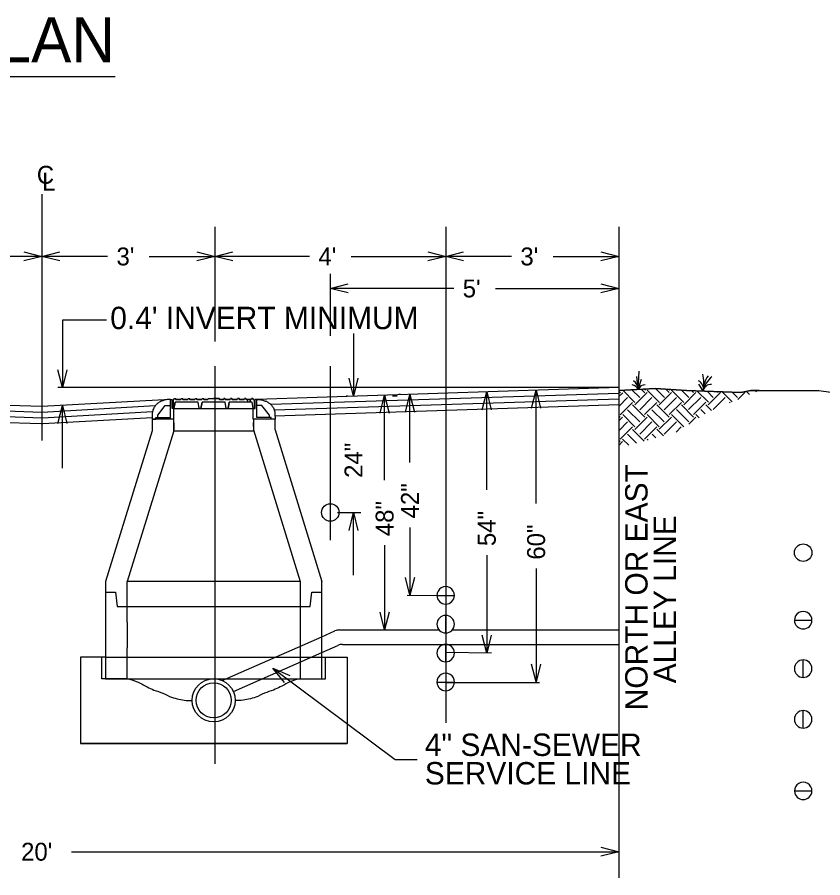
# Model space of a CAD drawing. Extents: x 524397 to 525117, y 3701341 to 3701821.
# Drawn here: x 524531 to 524603, y 3701447.4 to 3701524.2 of the extents above; entities that cross this region are included whole.
import ezdxf

# ---------------------------------------------------------------- set-up
doc = ezdxf.new("R2010")
doc.units = 0
doc.layers.add('Level 1', color=7, linetype='Continuous')
doc.layers.add('Level 11', color=7, linetype='Continuous')

msp = doc.modelspace()

# ---------------------------------------------------------------- linework, layer by layer
at = {"layer": 'Level 1'}
for p, q in [((524526.598, 3701518.966), (524539.734, 3701518.966)), ((524533.168, 3701508.449), (524533.168, 3701486.42)), ((524548.636, 3701505.51), (524548.636, 3701495.288)), ((524569.261, 3701505.51), (524569.261, 3701461.218)), ((524584.73, 3701505.51), (524584.73, 3701447.362)), ((524558.949, 3701501.319), (524558.949, 3701495.77)), ((524548.636, 3701493.058), (524548.636, 3701457.545)), ((524558.949, 3701493.058), (524558.949, 3701477.535)), ((524586.467, 3701490.993), (524586.344, 3701492.151)), ((524586.467, 3701490.993), (524586.554, 3701492.625)), ((524586.467, 3701490.993), (524586.765, 3701491.923)), ((524533.168, 3701489.455), (524486.759, 3701491.156)), ((524533.151, 3701488.939), (524487.926, 3701490.601)), ((524584.73, 3701491.156), (524534.586, 3701491.156)), ((524584.73, 3701491.156), (524552.385, 3701490.108)), ((524584.73, 3701490.64), (524553.646, 3701489.633)), ((524587.984, 3701491.074), (524584.73, 3701490.9)), ((524584.73, 3701490.9), (524587.984, 3701491.074)), ((524584.73, 3701490.9), (524584.73, 3701485.763)), ((524584.73, 3701490.847), (524584.875, 3701490.702)), ((524584.73, 3701490.354), (524585.078, 3701490.702)), ((524585.08, 3701490.919), (524586.172, 3701489.827)), ((524585.911, 3701490.963), (524586.609, 3701490.265)), ((524586.164, 3701489.616), (524587.258, 3701490.71)), ((524586.741, 3701491.008), (524587.047, 3701490.702)), ((524587.047, 3701490.921), (524587.156, 3701491.03)), ((524587.274, 3701490.929), (524588.368, 3701489.835)), ((524590.772, 3701490.9), (524587.984, 3701491.074)), ((524587.984, 3701491.074), (524590.772, 3701490.9)), ((524588.005, 3701491.073), (524588.805, 3701490.273)), ((524588.352, 3701489.616), (524589.446, 3701490.71)), ((524588.938, 3701491.015), (524589.243, 3701490.71)), ((524589.227, 3701490.928), (524589.291, 3701490.993)), ((524589.446, 3701490.928), (524590.539, 3701489.835)), ((524590.321, 3701490.929), (524590.977, 3701490.272)), ((524590.532, 3701489.624), (524591.626, 3701490.717)), ((524595.652, 3701490.727), (524590.772, 3701490.9)), ((524590.772, 3701490.9), (524595.652, 3701490.727)), ((524591.24, 3701490.884), (524591.414, 3701490.71)), ((524591.711, 3701490.867), (524592.735, 3701489.843)), ((524592.618, 3701490.835), (524593.173, 3701490.28)), ((524592.719, 3701489.624), (524593.813, 3701490.717)), ((524593.526, 3701490.802), (524593.61, 3701490.718)), ((524593.962, 3701490.787), (524594.863, 3701489.886)), ((524594.87, 3701490.754), (524595.345, 3701490.28)), ((524595.363, 3701490.095), (524595.993, 3701490.725)), ((524596.523, 3701490.9), (524595.652, 3701490.727)), ((524595.652, 3701490.727), (524596.523, 3701490.9)), ((524595.753, 3701490.747), (524595.782, 3701490.717)), ((524596.131, 3701490.822), (524596.417, 3701490.536)), ((524597.29, 3701490.9), (524596.523, 3701490.9)), ((524596.523, 3701490.9), (524598.439, 3701490.9)), ((524596.928, 3701490.9), (524597.034, 3701490.794)), ((524598.439, 3701490.9), (524599.485, 3701490.9)), ((524599.485, 3701490.9), (524602.622, 3701490.9)), ((524602.622, 3701490.9), (524606.455, 3701490.379)), ((524533.134, 3701488.423), (524487.994, 3701490.083)), ((524544.655, 3701490.108), (524533.168, 3701489.455)), ((524544.655, 3701490.108), (524544.655, 3701490.108)), ((524544.655, 3701490.108), (524544.817, 3701490.108)), ((524544.655, 3701489.545), (524544.655, 3701490.108)), ((524544.816, 3701489.303), (524544.817, 3701490.108)), ((524544.896, 3701490.108), (524544.896, 3701489.303)), ((524544.978, 3701490.108), (524544.896, 3701490.108)), ((524544.977, 3701489.303), (524545.076, 3701489.867)), ((524544.978, 3701490.108), (524545.008, 3701490.188)), ((524545.008, 3701490.188), (524545.128, 3701490.188)), ((524547.132, 3701489.867), (524545.076, 3701489.867)), ((524545.158, 3701490.108), (524545.128, 3701490.188)), ((524545.604, 3701490.108), (524545.158, 3701490.108)), ((524545.604, 3701490.108), (524545.634, 3701490.188)), ((524545.634, 3701490.188), (524545.749, 3701490.188)), ((524545.778, 3701490.108), (524545.749, 3701490.188)), ((524546.216, 3701490.108), (524545.778, 3701490.108)), ((524546.216, 3701490.108), (524546.245, 3701490.188)), ((524546.245, 3701490.188), (524546.376, 3701490.188)), ((524546.406, 3701490.108), (524546.376, 3701490.188)), ((524546.849, 3701490.108), (524546.406, 3701490.108)), ((524546.849, 3701490.108), (524546.879, 3701490.188)), ((524546.879, 3701490.188), (524547.004, 3701490.188)), ((524547.034, 3701490.108), (524547.004, 3701490.188)), ((524547.473, 3701490.108), (524547.034, 3701490.108)), ((524547.231, 3701489.303), (524547.132, 3701489.867)), ((524547.393, 3701489.303), (524547.493, 3701489.867)), ((524547.473, 3701490.108), (524547.502, 3701490.188)), ((524549.547, 3701489.867), (524547.493, 3701489.867)), ((524547.502, 3701490.188), (524547.614, 3701490.188)), ((524547.644, 3701490.108), (524547.614, 3701490.188)), ((524548.005, 3701490.108), (524547.644, 3701490.108)), ((524548.005, 3701490.108), (524548.035, 3701490.188)), ((524548.035, 3701490.188), (524548.519, 3701490.188)), ((524549.005, 3701490.188), (524548.519, 3701490.188)), ((524549.035, 3701490.108), (524549.005, 3701490.188)), ((524549.396, 3701490.108), (524549.035, 3701490.108)), ((524549.396, 3701490.108), (524549.425, 3701490.188)), ((524549.538, 3701490.188), (524549.425, 3701490.188)), ((524549.568, 3701490.108), (524549.538, 3701490.188)), ((524549.647, 3701489.303), (524549.547, 3701489.867)), ((524550.006, 3701490.108), (524549.568, 3701490.108)), ((524549.808, 3701489.303), (524549.906, 3701489.867)), ((524551.963, 3701489.867), (524549.906, 3701489.867)), ((524550.006, 3701490.108), (524550.036, 3701490.188)), ((524550.162, 3701490.188), (524550.036, 3701490.188)), ((524550.191, 3701490.108), (524550.162, 3701490.188)), ((524550.633, 3701490.108), (524550.191, 3701490.108)), ((524550.633, 3701490.108), (524550.662, 3701490.188)), ((524550.795, 3701490.188), (524550.662, 3701490.188)), ((524550.823, 3701490.108), (524550.795, 3701490.188)), ((524551.262, 3701490.108), (524550.823, 3701490.108)), ((524551.262, 3701490.108), (524551.29, 3701490.188)), ((524551.405, 3701490.188), (524551.29, 3701490.188)), ((524551.434, 3701490.108), (524551.405, 3701490.188)), ((524551.882, 3701490.108), (524551.434, 3701490.108)), ((524551.539, 3701490.108), (524551.539, 3701489.867)), ((524551.78, 3701490.108), (524551.78, 3701489.867)), ((524551.882, 3701490.108), (524551.911, 3701490.188)), ((524552.032, 3701490.188), (524551.911, 3701490.188)), ((524552.063, 3701489.303), (524551.963, 3701489.867)), ((524552.061, 3701490.108), (524552.032, 3701490.188)), ((524552.142, 3701490.108), (524552.061, 3701490.108)), ((524552.142, 3701490.108), (524552.142, 3701489.303)), ((524552.224, 3701489.303), (524552.223, 3701490.108)), ((524552.385, 3701490.108), (524552.223, 3701490.108)), ((524552.385, 3701489.545), (524552.385, 3701490.108)), ((524584.73, 3701490.124), (524553.954, 3701489.127)), ((524560.474, 3701490.391), (524560.378, 3701490.391)), ((524564.51, 3701490.412), (524564.923, 3701490.412)), ((524565.21, 3701490.544), (524565.079, 3701490.544)), ((524584.73, 3701489.479), (524585.516, 3701490.265)), ((524584.859, 3701488.733), (524585.953, 3701489.827)), ((524586.602, 3701489.178), (524587.696, 3701490.272)), ((524587.039, 3701488.741), (524588.133, 3701489.835)), ((524588.789, 3701489.178), (524589.883, 3701490.272)), ((524589.227, 3701488.741), (524590.321, 3701489.835)), ((524590.969, 3701489.186), (524592.063, 3701490.28)), ((524591.407, 3701488.749), (524592.501, 3701489.842)), ((524593.157, 3701489.186), (524594.251, 3701490.28)), ((524594.638, 3701489.792), (524594.688, 3701489.842)), ((524533.117, 3701487.908), (524488.061, 3701489.565)), ((524543.294, 3701489.514), (524533.196, 3701488.94)), ((524543.529, 3701488.7), (524544.205, 3701489.546)), ((524544.205, 3701489.546), (524544.655, 3701489.545)), ((524544.655, 3701488.498), (524544.655, 3701489.545)), ((524544.977, 3701489.303), (524544.816, 3701489.303)), ((524544.896, 3701489.303), (524552.142, 3701489.303)), ((524544.977, 3701488.336), (524544.977, 3701489.303)), ((524552.063, 3701488.336), (524552.063, 3701489.303)), ((524552.063, 3701489.303), (524552.224, 3701489.303)), ((524552.835, 3701489.546), (524552.385, 3701489.545)), ((524552.385, 3701488.498), (524552.385, 3701489.545)), ((524553.511, 3701488.7), (524552.835, 3701489.546)), ((524584.73, 3701489.608), (524554.004, 3701488.613)), ((524585.524, 3701489.179), (524586.617, 3701488.085)), ((524585.961, 3701489.616), (524587.055, 3701488.523)), ((524587.696, 3701489.178), (524588.789, 3701488.085)), ((524588.133, 3701489.616), (524589.227, 3701488.522)), ((524589.891, 3701489.186), (524590.985, 3701488.093)), ((524590.329, 3701489.624), (524591.423, 3701488.53)), ((524592.063, 3701489.186), (524592.449, 3701488.801)), ((524592.501, 3701489.624), (524593.012, 3701489.112)), ((524543.064, 3701488.984), (524533.226, 3701488.425)), ((524543.029, 3701488.465), (524533.255, 3701487.91)), ((524543.024, 3701488.336), (524543.024, 3701487.305)), ((524543.024, 3701488.336), (524543.366, 3701488.336)), ((524544.977, 3701488.336), (524543.024, 3701488.336)), ((524543.366, 3701488.336), (524543.366, 3701488.498)), ((524543.366, 3701488.498), (524543.528, 3701488.498)), ((524543.528, 3701488.498), (524543.529, 3701488.7)), ((524543.528, 3701488.498), (524544.655, 3701488.498)), ((524544.957, 3701487.306), (524544.957, 3701488.336)), ((524554.016, 3701488.336), (524552.063, 3701488.336)), ((524552.083, 3701488.336), (524552.083, 3701487.371)), ((524554.016, 3701488.336), (524552.083, 3701488.336)), ((524553.512, 3701488.498), (524552.385, 3701488.498)), ((524553.512, 3701488.498), (524553.511, 3701488.7)), ((524553.672, 3701488.498), (524553.512, 3701488.498)), ((524553.672, 3701488.336), (524553.672, 3701488.498)), ((524554.016, 3701488.336), (524553.672, 3701488.336)), ((524554.015, 3701487.371), (524554.015, 3701488.336)), ((524584.73, 3701488.644), (524584.859, 3701488.514)), ((524584.73, 3701488.182), (524585.07, 3701488.522)), ((524585.086, 3701488.741), (524586.18, 3701487.647)), ((524586.164, 3701487.428), (524587.258, 3701488.522)), ((524587.258, 3701488.741), (524588.352, 3701487.647)), ((524588.344, 3701487.436), (524589.438, 3701488.53)), ((524589.454, 3701488.749), (524590.548, 3701487.655)), ((524590.996, 3701487.9), (524591.626, 3701488.53)), ((524591.626, 3701488.749), (524591.908, 3701488.466)), ((524544.957, 3701488.015), (524544.957, 3701487.384)), ((524552.083, 3701487.693), (524552.083, 3701488.028)), ((524584.73, 3701487.307), (524585.508, 3701488.085)), ((524584.852, 3701486.553), (524585.945, 3701487.647)), ((524586.602, 3701486.991), (524587.696, 3701488.085)), ((524587.039, 3701486.553), (524588.133, 3701487.647)), ((524588.782, 3701486.998), (524589.875, 3701488.092)), ((524589.846, 3701487.187), (524590.313, 3701487.655)), ((524543.024, 3701487.305), (524538.866, 3701473.834)), ((524544.957, 3701487.306), (524540.798, 3701473.835)), ((524544.957, 3701487.306), (524552.083, 3701487.306)), ((524552.083, 3701487.371), (524556.258, 3701473.843)), ((524554.015, 3701487.371), (524558.191, 3701473.843)), ((524585.508, 3701486.991), (524586.309, 3701486.189)), ((524585.945, 3701487.428), (524586.998, 3701486.376)), ((524587.704, 3701486.999), (524588.044, 3701486.658)), ((524588.141, 3701487.436), (524588.733, 3701486.845)), ((524584.73, 3701486.472), (524584.867, 3701486.335)), ((524584.73, 3701485.994), (524585.07, 3701486.334)), ((524585.07, 3701486.553), (524585.62, 3701486.003)), ((524587.266, 3701486.561), (524587.355, 3701486.472)), ((524559.593, 3701480.003), (524561.667, 3701480.003)), ((524538.866, 3701473.834), (524538.866, 3701471.589)), ((524556.258, 3701473.842), (524540.798, 3701473.835)), ((524540.798, 3701471.589), (524540.798, 3701473.835)), ((524556.258, 3701473.843), (524556.258, 3701471.589)), ((524556.258, 3701473.843), (524556.258, 3701472.877)), ((524558.191, 3701472.877), (524558.191, 3701473.843)), ((524558.191, 3701472.877), (524558.191, 3701473.843)), ((524538.866, 3701473.268), (524538.866, 3701472.877)), ((524540.798, 3701472.877), (524540.798, 3701473.268)), ((524556.258, 3701473.268), (524556.258, 3701472.877)), ((524556.258, 3701473.268), (524556.258, 3701472.877)), ((524558.191, 3701465.148), (524558.191, 3701473.268)), ((524538.866, 3701472.877), (524539.752, 3701472.877)), ((524538.866, 3701472.877), (524539.752, 3701472.877)), ((524538.866, 3701472.877), (524538.866, 3701470.194)), ((524538.866, 3701472.127), (524538.866, 3701465.148)), ((524539.752, 3701472.877), (524539.913, 3701471.589)), ((524539.752, 3701472.877), (524539.913, 3701471.589)), ((524540.798, 3701470.194), (524540.798, 3701472.877)), ((524556.258, 3701472.877), (524556.258, 3701465.148)), ((524556.258, 3701472.877), (524556.258, 3701465.148)), ((524557.144, 3701471.589), (524557.305, 3701472.877)), ((524557.144, 3701471.589), (524557.305, 3701472.877)), ((524557.305, 3701472.877), (524558.191, 3701472.877)), ((524557.305, 3701472.877), (524558.191, 3701472.877)), ((524557.305, 3701472.877), (524558.191, 3701472.877)), ((524558.191, 3701471.589), (524558.191, 3701472.877)), ((524565.813, 3701472.598), (524569.413, 3701472.585)), ((524568.479, 3701472.585), (524570.044, 3701472.585)), ((524539.913, 3701471.589), (524540.798, 3701471.589)), ((524539.913, 3701471.589), (524540.798, 3701471.589)), ((524540.798, 3701471.589), (524556.258, 3701471.589)), ((524540.798, 3701471.589), (524556.258, 3701471.589)), ((524556.258, 3701471.589), (524557.144, 3701471.589)), ((524556.258, 3701471.589), (524557.144, 3701471.589)), ((524569.261, 3701469.237), (524569.261, 3701470.801)), ((524569.261, 3701470.801), (524569.261, 3701470.801)), ((524540.798, 3701470.194), (524540.798, 3701467.905)), ((524600.43, 3701470.365), (524601.995, 3701470.365)), ((524558.191, 3701468.899), (524559.366, 3701469.415)), ((524559.781, 3701469.503), (524568.673, 3701469.503)), ((524569.849, 3701469.503), (524584.73, 3701469.503)), ((524549.295, 3701464.989), (524558.191, 3701468.899)), ((524540.798, 3701465.148), (524540.798, 3701467.905)), ((524558.191, 3701467.491), (524559.637, 3701468.126)), ((524560.051, 3701468.214), (524584.73, 3701468.214)), ((524569.261, 3701466.657), (524569.261, 3701468.222)), ((524569.261, 3701468.222), (524569.261, 3701468.222)), ((524569.261, 3701467.521), (524573.348, 3701467.473)), ((524538.866, 3701467.081), (524536.612, 3701467.081)), ((524536.612, 3701467.081), (524536.612, 3701459.351)), ((524538.544, 3701465.148), (524538.544, 3701467.081)), ((524538.866, 3701467.081), (524558.191, 3701467.081)), ((524550.287, 3701464.017), (524558.191, 3701467.491)), ((524558.191, 3701467.081), (524560.445, 3701467.081)), ((524558.512, 3701465.148), (524558.512, 3701467.081)), ((524560.445, 3701467.081), (524560.445, 3701459.351)), ((524601.213, 3701465.265), (524601.213, 3701466.83)), ((524601.213, 3701466.83), (524601.213, 3701466.83)), ((524538.866, 3701465.148), (524538.544, 3701465.148)), ((524538.866, 3701465.148), (524538.544, 3701465.148)), ((524538.866, 3701465.148), (524540.798, 3701465.148)), ((524540.798, 3701465.148), (524538.866, 3701465.148)), ((524540.798, 3701465.148), (524538.866, 3701465.148)), ((524540.798, 3701465.148), (524556.258, 3701465.148)), ((524556.258, 3701465.148), (524558.191, 3701465.148)), ((524556.258, 3701465.148), (524558.191, 3701465.148)), ((524558.191, 3701465.148), (524558.512, 3701465.148)), ((524570.043, 3701464.823), (524568.48, 3701464.823)), ((524569.269, 3701464.823), (524577.64, 3701464.823)), ((524570.043, 3701464.823), (524570.043, 3701464.823)), ((524601.213, 3701460.741), (524601.213, 3701462.305)), ((524601.213, 3701462.305), (524601.213, 3701462.305)), ((524560.445, 3701459.351), (524536.612, 3701459.351)), ((524536.612, 3701459.351), (524560.445, 3701459.351)), ((524601.994, 3701455.717), (524601.994, 3701455.717)), ((524601.994, 3701455.092), (524600.431, 3701455.092))]:
    msp.add_line(p, q, dxfattribs=at)
for points in [[(524544.896, 3701490.108), (524544.978, 3701490.108), (524545.008, 3701490.188), (524545.128, 3701490.188), (524545.158, 3701490.108), (524545.604, 3701490.108), (524545.634, 3701490.188), (524545.749, 3701490.188), (524545.778, 3701490.108), (524546.216, 3701490.108), (524546.245, 3701490.188), (524546.376, 3701490.188), (524546.406, 3701490.108), (524546.849, 3701490.108), (524546.879, 3701490.188), (524547.004, 3701490.188), (524547.034, 3701490.108), (524547.473, 3701490.108), (524547.502, 3701490.188), (524547.614, 3701490.188), (524547.644, 3701490.108), (524548.005, 3701490.108), (524548.035, 3701490.188), (524549.005, 3701490.188), (524549.035, 3701490.108), (524549.396, 3701490.108), (524549.425, 3701490.188), (524549.538, 3701490.188), (524549.568, 3701490.108), (524550.006, 3701490.108), (524550.036, 3701490.188), (524550.162, 3701490.188), (524550.191, 3701490.108), (524550.633, 3701490.108), (524550.662, 3701490.188), (524550.795, 3701490.188), (524550.823, 3701490.108), (524551.262, 3701490.108), (524551.29, 3701490.188), (524551.405, 3701490.188), (524551.434, 3701490.108), (524551.539, 3701490.108), (524551.539, 3701489.867), (524549.906, 3701489.867), (524549.808, 3701489.303), (524549.647, 3701489.303), (524549.547, 3701489.867), (524547.493, 3701489.867), (524547.393, 3701489.303), (524547.231, 3701489.303), (524547.132, 3701489.867), (524545.076, 3701489.867), (524544.977, 3701489.303), (524544.896, 3701489.303)], [(524551.78, 3701490.108), (524551.882, 3701490.108), (524551.911, 3701490.188), (524552.032, 3701490.188), (524552.061, 3701490.108), (524552.142, 3701490.108), (524552.142, 3701489.303), (524552.063, 3701489.303), (524551.963, 3701489.867), (524551.78, 3701489.867)]]:
    msp.add_lwpolyline(points, close=True, dxfattribs=at)
for centre, radius in [((524558.949, 3701480.002), 0.782), ((524601.212, 3701476.412), 0.782), ((524548.528, 3701463.215), 1.932), ((524548.528, 3701463.215), 1.574)]:
    msp.add_circle(centre, radius, dxfattribs=at)
for centre, radius, start, end in [((524589.098, 3701491.534), 3.241, 347.86335, 14.79836), ((524594.598, 3701490.842), 2.331, 144.24602, 179.72588), ((524594.426, 3701490.399), 2.207, 128.91085, 168.13547), ((524585.678, 3701490.546), 0.907, 29.52947, 73.2466), ((524585.528, 3701490.981), 0.938, 0.70535, 56.60134), ((524587.078, 3701490.76), 0.654, 88.13887, 159.17659), ((524591.501, 3701491.052), 0.791, 345.39087, 64.24154), ((524619.775, 3701509.928), 33.474, 213.50539, 214.73889), ((524592.968, 3701490.741), 0.71, 85.61557, 170.94701), ((524569.261, 3701472.598), 0.782, 359.05595, 180.94414), ((524569.261, 3701472.598), 0.782, 180.94405, 359.05595), ((524569.261, 3701470.018), 0.782, 90, 270), ((524569.261, 3701470.018), 0.782, 270, 90), ((524601.212, 3701470.377), 0.782, 359.05595, 180.94414), ((524601.212, 3701470.377), 0.782, 180.94405, 359.05595), ((524559.781, 3701468.471), 1.031, 90, 113.73944), ((524560.051, 3701467.182), 1.031, 90, 113.71222), ((524569.261, 3701467.439), 0.782, 90, 270), ((524569.261, 3701467.439), 0.782, 270, 90), ((524601.212, 3701466.047), 0.782, 90, 270), ((524601.212, 3701466.047), 0.782, 270, 90), ((524569.261, 3701464.86), 0.782, 357.28024, 182.68142), ((524569.261, 3701464.86), 0.782, 182.68197, 357.28024), ((524601.212, 3701461.523), 0.782, 90, 270), ((524601.212, 3701461.523), 0.782, 270, 90), ((524601.212, 3701455.128), 0.782, 357.28024, 182.68142), ((524601.212, 3701455.128), 0.782, 182.68197, 357.28024)]:
    msp.add_arc(centre, radius, start, end, dxfattribs=at)
for points in [[(524544.655, 3701490.108), (524544.514, 3701490.106), (524544.361, 3701490.086), (524544.227, 3701490.063), (524544.113, 3701490.039), (524543.991, 3701489.986), (524543.878, 3701489.96), (524543.601, 3701489.806), (524543.4, 3701489.64), (524543.224, 3701489.411), (524543.077, 3701489.094), (524543.037, 3701488.645), (524543.024, 3701488.336)], [(524552.385, 3701490.108), (524552.525, 3701490.106), (524552.678, 3701490.086), (524552.811, 3701490.063), (524552.925, 3701490.039), (524553.049, 3701489.986), (524553.162, 3701489.96), (524553.439, 3701489.806), (524553.639, 3701489.64), (524553.815, 3701489.411), (524553.962, 3701489.094), (524554.002, 3701488.645), (524554.015, 3701488.336)], [(524540.798, 3701465.148), (524541.6, 3701464.907), (524542.573, 3701464.421), (524543.183, 3701464.137), (524543.994, 3701463.853), (524544.766, 3701463.488), (524545.416, 3701463.326), (524546.064, 3701463.205), (524546.596, 3701463.215)], [(524556.258, 3701465.148), (524555.458, 3701464.907), (524554.483, 3701464.421), (524553.874, 3701464.137), (524553.062, 3701463.853), (524552.291, 3701463.488), (524551.642, 3701463.326), (524550.991, 3701463.205), (524550.46, 3701463.215)]]:
    msp.add_spline(points, degree=3, dxfattribs=at)
at = {"layer": 'Level 11'}
for p, q in [((524531.567, 3701503.274), (524533.168, 3701502.874)), ((524533.168, 3701502.874), (524534.769, 3701503.274)), ((524547.035, 3701503.274), (524548.636, 3701502.874)), ((524548.636, 3701502.874), (524550.237, 3701503.274)), ((524567.66, 3701503.274), (524569.261, 3701502.874)), ((524569.261, 3701502.874), (524570.862, 3701503.274)), ((524583.129, 3701503.274), (524584.73, 3701502.874)), ((524533.168, 3701502.874), (524529.447, 3701502.874)), ((524533.168, 3701502.874), (524531.567, 3701502.474)), ((524539.043, 3701502.874), (524533.168, 3701502.874)), ((524534.769, 3701502.474), (524533.168, 3701502.874)), ((524542.761, 3701502.874), (524548.636, 3701502.874)), ((524548.636, 3701502.874), (524547.035, 3701502.474)), ((524557.09, 3701502.874), (524548.636, 3701502.874)), ((524550.237, 3701502.474), (524548.636, 3701502.874)), ((524560.808, 3701502.874), (524569.261, 3701502.874)), ((524569.261, 3701502.874), (524567.66, 3701502.474)), ((524575.136, 3701502.874), (524569.261, 3701502.874)), ((524570.862, 3701502.474), (524569.261, 3701502.874)), ((524578.855, 3701502.874), (524584.73, 3701502.874)), ((524584.73, 3701502.874), (524583.129, 3701502.474)), ((524558.949, 3701500.014), (524560.55, 3701500.414)), ((524569.98, 3701500.014), (524558.949, 3701500.014)), ((524560.55, 3701499.614), (524558.949, 3701500.014)), ((524573.699, 3701500.014), (524584.73, 3701500.014)), ((524583.129, 3701500.414), (524584.73, 3701500.014)), ((524584.73, 3701500.014), (524583.129, 3701499.614)), ((524538.937, 3701497.176), (524535.009, 3701497.176)), ((524535.009, 3701497.176), (524535.009, 3701491.156)), ((524561.022, 3701495.992), (524561.022, 3701490.389)), ((524535.009, 3701495.159), (524535.009, 3701491.156)), ((524535.009, 3701491.156), (524534.609, 3701492.757)), ((524535.409, 3701492.757), (524535.009, 3701491.156)), ((524561.022, 3701490.389), (524560.622, 3701491.99)), ((524561.423, 3701491.99), (524561.022, 3701490.389)), ((524572.533, 3701489.167), (524572.933, 3701490.768)), ((524572.933, 3701482.009), (524572.933, 3701490.768)), ((524572.933, 3701490.768), (524573.333, 3701489.167)), ((524576.941, 3701489.314), (524577.341, 3701490.915)), ((524577.341, 3701480.793), (524577.341, 3701490.915)), ((524577.341, 3701490.915), (524577.741, 3701489.314)), ((524563.403, 3701488.875), (524563.804, 3701490.476)), ((524563.804, 3701482.895), (524563.804, 3701490.476)), ((524563.804, 3701490.476), (524564.204, 3701488.875)), ((524565.67, 3701488.951), (524566.07, 3701490.552)), ((524566.07, 3701484.48), (524566.07, 3701490.552)), ((524566.07, 3701490.552), (524566.47, 3701488.951)), ((524534.609, 3701487.963), (524535.009, 3701489.564)), ((524535.009, 3701483.96), (524535.009, 3701489.564)), ((524535.009, 3701489.564), (524535.409, 3701487.963)), ((524560.622, 3701478.401), (524561.022, 3701480.002)), ((524561.022, 3701474.399), (524561.022, 3701480.002)), ((524561.022, 3701480.002), (524561.423, 3701478.401)), ((524566.07, 3701478.669), (524566.07, 3701472.598)), ((524563.804, 3701477.084), (524563.804, 3701469.503)), ((524572.933, 3701476.198), (524572.933, 3701467.439)), ((524577.341, 3701474.982), (524577.341, 3701464.86)), ((524566.07, 3701472.598), (524565.67, 3701474.199)), ((524566.47, 3701474.199), (524566.07, 3701472.598)), ((524563.804, 3701469.503), (524563.403, 3701471.104)), ((524564.204, 3701471.104), (524563.804, 3701469.503)), ((524572.933, 3701467.439), (524572.533, 3701469.04)), ((524573.333, 3701469.04), (524572.933, 3701467.439)), ((524554.853, 3701464.799), (524553.808, 3701466.076)), ((524553.808, 3701466.076), (524555.331, 3701465.441)), ((524553.808, 3701466.076), (524564.75, 3701457.931)), ((524577.341, 3701464.86), (524576.941, 3701466.461)), ((524577.741, 3701466.461), (524577.341, 3701464.86)), ((524564.75, 3701457.931), (524566.721, 3701457.931)), ((524583.129, 3701450.091), (524584.73, 3701449.691)), ((524535.821, 3701449.691), (524584.73, 3701449.691)), ((524584.73, 3701449.691), (524583.129, 3701449.29))]:
    msp.add_line(p, q, dxfattribs=at)

# ---------------------------------------------------------------- texts
at = {"layer": 'Level 1'}
for s, height, p in [('PLAN', 4.0362, (524525.613, 3701520.213)), ('C', 1.601, (524532.719, 3701509.368)), ('L', 1.601, (524533.202, 3701508.765)), ("0.4' INVERT MINIMUM", 2, (524539.282, 3701496.38)), ('4" SAN-SEWER', 2, (524567.396, 3701458.247)), ('SERVICE LINE', 2, (524567.396, 3701455.701))]:
    msp.add_text(s, height=height, dxfattribs=at).set_placement(p)
at = {"layer": 'Level 11'}
for s, p in [("3'", (524539.843, 3701502.074)), ("4'", (524557.89, 3701502.074)), ("3'", (524575.937, 3701502.074)), ("5'", (524570.781, 3701499.214)), ("20'", (524531.315, 3701448.89))]:
    msp.add_text(s, height=1.601, dxfattribs=at).set_placement(p)
for s, height, p in [('24"', 1.601, (524561.823, 3701483.09)), ('NORTH OR EAST', 2, (524587.302, 3701462.325)), ('42"', 1.601, (524566.87, 3701479.47)), ('48"', 1.601, (524564.604, 3701477.884)), ('54"', 1.601, (524573.733, 3701476.998)), ('ALLEY LINE', 2, (524589.848, 3701464.739)), ('60"', 1.601, (524578.141, 3701475.782))]:
    msp.add_text(s, height=height, rotation=90, dxfattribs=at).set_placement(p)

doc.saveas('drawing.dxf')
